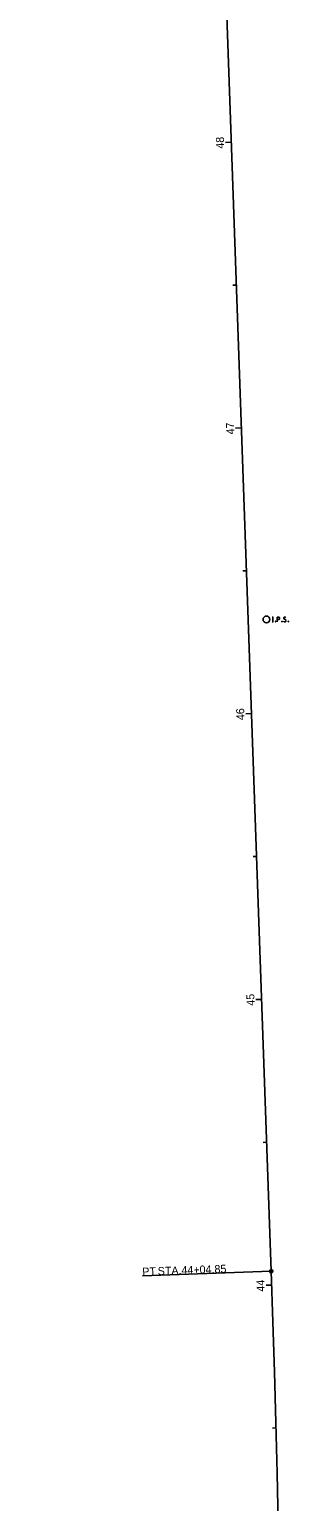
# Model space of a CAD drawing. Extents: x 146022 to 147490, y 436269 to 440659.
# Drawn here: x 146946 to 147037, y 437317 to 437832 of the extents above; entities that cross this region are included whole.
import ezdxf

# ---------------------------------------------------------------- set-up
doc = ezdxf.new("R2010")
doc.units = 0
for name, color, linetype in [('RW_X_CL', 7, 'Continuous'), ('RW_X_CL_100_Cardinal_Points', 7, 'Continuous'), ('RW_X_CL_100_Stations', 7, 'Continuous'), ('SV_P_Mon_Cells_Set', 7, 'Continuous')]:
    doc.layers.add(name, color=color, linetype=linetype)

msp = doc.modelspace()

# ---------------------------------------------------------------- linework, layer by layer
at = {"layer": 'RW_X_CL'}
msp.add_line((147030.73, 437397.38), (146946.25, 439782.71), dxfattribs=at)
msp.add_arc((141304.74, 437194.59), 5729.58, 350.738365, 2.02828, dxfattribs=at)
at = {"layer": 'RW_X_CL_100_Cardinal_Points'}
msp.add_line((147030.73, 437397.38), (146985.76, 437395.79), dxfattribs=at)
msp.add_circle((147030.73, 437397.38), 0.6, dxfattribs=at)
at = {"layer": 'RW_X_CL_100_Stations'}
for p, q in [((147016.74, 437792.28), (147014.75, 437792.21)), ((147018.51, 437742.31), (147017.31, 437742.27)), ((147020.28, 437692.34), (147018.28, 437692.27)), ((147022.05, 437642.38), (147020.85, 437642.33)), ((147023.82, 437592.41), (147021.82, 437592.34)), ((147025.59, 437542.44), (147024.39, 437542.4)), ((147027.36, 437492.47), (147025.36, 437492.4)), ((147029.13, 437442.5), (147027.93, 437442.46)), ((147030.9, 437392.53), (147028.9, 437392.46)), ((147032.41, 437342.56), (147031.21, 437342.52))]:
    msp.add_line(p, q, dxfattribs=at)
at = {"layer": 'SV_P_Mon_Cells_Set'}
for points in [[(147031.08, 437626.15), (147031.43, 437626.15)], [(147031.08, 437624.55), (147031.43, 437624.55)], [(147031.26, 437624.55), (147031.26, 437626.15)], [(147032.22, 437624.77), (147032.27, 437624.77), (147032.3, 437624.74), (147032.34, 437624.69), (147032.34, 437624.63), (147032.3, 437624.58), (147032.27, 437624.55), (147032.22, 437624.55), (147032.18, 437624.58), (147032.15, 437624.63), (147032.15, 437624.69), (147032.18, 437624.74), (147032.22, 437624.77)], [(147032.82, 437624.55), (147032.82, 437626.15), (147033.35, 437626.15), (147033.41, 437626.14), (147033.48, 437626.12), (147033.52, 437626.09), (147033.55, 437626.07), (147033.59, 437626), (147033.63, 437625.94), (147033.65, 437625.84), (147033.65, 437625.69), (147033.64, 437625.64), (147033.62, 437625.56), (147033.57, 437625.47), (147033.53, 437625.44), (147033.49, 437625.41), (147033.44, 437625.39), (147033.35, 437625.37), (147032.82, 437625.37)], [(147034.46, 437624.77), (147034.52, 437624.77), (147034.55, 437624.74), (147034.59, 437624.69), (147034.59, 437624.63), (147034.55, 437624.58), (147034.52, 437624.55), (147034.46, 437624.55), (147034.43, 437624.58), (147034.4, 437624.63), (147034.4, 437624.69), (147034.43, 437624.74), (147034.46, 437624.77)], [(147035.83, 437626.04), (147035.81, 437626.07), (147035.78, 437626.09), (147035.68, 437626.13), (147035.56, 437626.15), (147035.47, 437626.15), (147035.43, 437626.15), (147035.29, 437626.12), (147035.17, 437626.04), (147035.09, 437625.94), (147035.07, 437625.84), (147035.07, 437625.76), (147035.09, 437625.66), (147035.18, 437625.57), (147035.79, 437625.2), (147035.84, 437625.15), (147035.86, 437625.1), (147035.89, 437625.02), (147035.89, 437624.94), (147035.88, 437624.87), (147035.86, 437624.82), (147035.84, 437624.76), (147035.82, 437624.7), (147035.8, 437624.67), (147035.76, 437624.63), (147035.73, 437624.6), (147035.69, 437624.58), (147035.65, 437624.57), (147035.56, 437624.55), (147035.4, 437624.55), (147035.3, 437624.58), (147035.16, 437624.67), (147035.07, 437624.74)], [(147036.65, 437624.77), (147036.7, 437624.77), (147036.73, 437624.74), (147036.77, 437624.69), (147036.77, 437624.63), (147036.73, 437624.58), (147036.7, 437624.55), (147036.65, 437624.55), (147036.61, 437624.58), (147036.58, 437624.63), (147036.58, 437624.69), (147036.61, 437624.74), (147036.65, 437624.77)]]:
    msp.add_lwpolyline(points, dxfattribs=at)
msp.add_circle((147029.06, 437625.35), 1.2, dxfattribs=at)

# ---------------------------------------------------------------- texts
at = {"layer": 'RW_X_CL_100_Cardinal_Points'}
for s, p in [('PT', (146985.72, 437395.82)), (' STA. ', (146990.07, 437395.98)), ('44+04.85', (146999.39, 437396.31))]:
    msp.add_text(s, height=2.8, rotation=2.0283, dxfattribs=at).set_placement(p)
at = {"layer": 'RW_X_CL_100_Stations'}
for s, rotation, p in [('48', 92.0283, (147014.32, 437790.06)), ('47', 92.0283, (147017.86, 437690.13)), ('46', 92.0283, (147021.4, 437590.18)), ('45', 92.0283, (147024.94, 437490.29)), ('44', 91.9798, (147028.48, 437390.28))]:
    msp.add_text(s, height=2.8, rotation=rotation, dxfattribs=at).set_placement(p)

doc.saveas('drawing.dxf')
